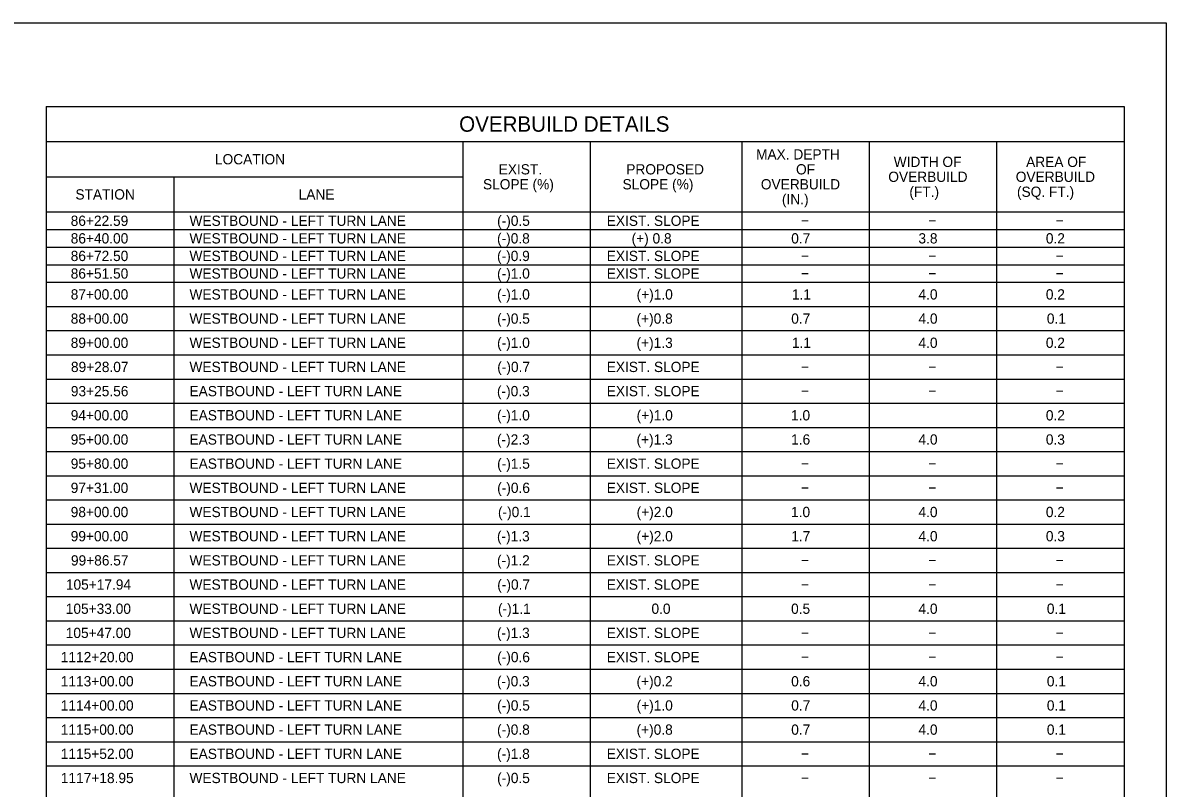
# Model space of a CAD drawing. Extents: x 0.03 to 1.66, y 0 to 0.87.
# Drawn here: x 0.679 to 1.329, y 0.436 to 0.871 of the extents above; entities that cross this region are included whole.
import ezdxf

# ---------------------------------------------------------------- set-up
doc = ezdxf.new("R2010")
doc.units = 0
for name, color, linetype in [('SheetBorder_dp', 7, 'Continuous'), ('SumBoxBorder_dp', 7, 'Continuous'), ('SumBoxLines_dp', 7, 'Continuous'), ('SumBoxLinesMin_dp', 7, 'Continuous'), ('TextLabel', 7, 'Continuous')]:
    doc.layers.add(name, color=color, linetype=linetype)

msp = doc.modelspace()

# ---------------------------------------------------------------- linework, layer by layer
at = {"layer": 'SheetBorder_dp'}
for p, q in [((0.04583, 0.87083), (1.32916, 0.87083)), ((1.32916, 0.87083), (1.32916, 0.00417))]:
    msp.add_line(p, q, dxfattribs=at)
at = {"layer": 'SumBoxBorder_dp'}
for p, q in [((0.69239, 0.82332), (1.30527, 0.82332)), ((1.30527, 0.82332), (1.30527, 0.10985)), ((1.30527, 0.82332), (1.30527, 0.10985))]:
    msp.add_line(p, q, dxfattribs=at)
at = {"layer": 'SumBoxLines_dp'}
for p, q in [((0.69239, 0.82332), (0.69239, 0.10985)), ((0.69239, 0.80332), (1.30527, 0.80332)), ((0.69239, 0.80332), (1.30527, 0.80332)), ((0.92917, 0.80332), (0.92917, 0.10985)), ((0.92917, 0.80332), (0.92917, 0.10985)), ((1.00164, 0.80332), (1.00164, 0.10985)), ((1.00164, 0.80332), (1.00164, 0.10985)), ((1.08785, 0.80332), (1.08785, 0.10985)), ((1.08785, 0.80332), (1.08785, 0.10985)), ((1.16032, 0.80332), (1.16032, 0.10985)), ((1.16032, 0.80332), (1.16032, 0.10985)), ((1.23279, 0.80332), (1.23279, 0.10985)), ((1.23279, 0.80332), (1.23279, 0.10985)), ((0.69239, 0.78333), (0.92917, 0.78333)), ((0.69239, 0.78333), (0.92917, 0.78333)), ((0.76486, 0.78333), (0.76486, 0.10985)), ((0.76486, 0.78333), (0.76486, 0.10985)), ((0.69239, 0.76334), (1.30527, 0.76334)), ((0.69239, 0.76334), (1.30527, 0.76334))]:
    msp.add_line(p, q, dxfattribs=at)
at = {"layer": 'SumBoxLinesMin_dp'}
for p, q in [((0.69239, 0.75334), (1.30527, 0.75334)), ((0.69239, 0.75334), (1.30527, 0.75334)), ((0.69239, 0.74335), (1.30527, 0.74335)), ((0.69239, 0.74335), (1.30527, 0.74335)), ((0.69239, 0.73335), (1.30527, 0.73335)), ((0.69239, 0.73335), (1.30527, 0.73335)), ((0.69239, 0.72336), (1.30527, 0.72336)), ((0.69239, 0.72336), (1.30527, 0.72336)), ((0.69239, 0.70961), (1.30527, 0.70961)), ((0.69239, 0.70961), (1.30527, 0.70961)), ((0.69239, 0.69587), (1.30527, 0.69587)), ((0.69239, 0.69587), (1.30527, 0.69587)), ((0.69239, 0.68212), (1.30527, 0.68212)), ((0.69239, 0.68212), (1.30527, 0.68212)), ((0.69239, 0.66838), (1.30527, 0.66838)), ((0.69239, 0.66838), (1.30527, 0.66838)), ((0.69239, 0.65463), (1.30527, 0.65463)), ((0.69239, 0.65463), (1.30527, 0.65463)), ((0.69239, 0.64089), (1.30527, 0.64089)), ((0.69239, 0.64089), (1.30527, 0.64089)), ((0.69239, 0.62714), (1.30527, 0.62714)), ((0.69239, 0.62714), (1.30527, 0.62714)), ((0.69239, 0.6134), (1.30527, 0.6134)), ((0.69239, 0.6134), (1.30527, 0.6134)), ((0.69239, 0.59966), (1.30527, 0.59966)), ((0.69239, 0.59966), (1.30527, 0.59966)), ((0.69239, 0.58591), (1.30527, 0.58591)), ((0.69239, 0.58591), (1.30527, 0.58591)), ((0.69239, 0.57217), (1.30527, 0.57217)), ((0.69239, 0.57217), (1.30527, 0.57217)), ((0.69239, 0.55842), (1.30527, 0.55842)), ((0.69239, 0.55842), (1.30527, 0.55842)), ((0.69239, 0.54468), (1.30527, 0.54468)), ((0.69239, 0.54468), (1.30527, 0.54468)), ((0.69239, 0.53093), (1.30527, 0.53093)), ((0.69239, 0.53093), (1.30527, 0.53093)), ((0.69239, 0.51719), (1.30527, 0.51719)), ((0.69239, 0.51719), (1.30527, 0.51719)), ((0.69239, 0.50344), (1.30527, 0.50344)), ((0.69239, 0.50344), (1.30527, 0.50344)), ((0.69239, 0.4897), (1.30527, 0.4897)), ((0.69239, 0.4897), (1.30527, 0.4897)), ((0.69239, 0.47596), (1.30527, 0.47596)), ((0.69239, 0.47596), (1.30527, 0.47596)), ((0.69239, 0.46221), (1.30527, 0.46221)), ((0.69239, 0.46221), (1.30527, 0.46221)), ((0.69239, 0.44847), (1.30527, 0.44847)), ((0.69239, 0.44847), (1.30527, 0.44847))]:
    msp.add_line(p, q, dxfattribs=at)

# ---------------------------------------------------------------- texts
at = {"layer": 'TextLabel'}
for s, height, p in [('OVERBUILD DETAILS', 0.0087465, (0.92717, 0.80895)), ('LOCATION', 0.005831, (0.78831, 0.79041)), ('MAX. DEPTH', 0.005831, (1.09598, 0.79316)), ('WIDTH OF', 0.005831, (1.17425, 0.78891)), ('AREA OF', 0.005831, (1.24955, 0.78891)), ('EXIST.', 0.005831, (0.94963, 0.78467)), ('PROPOSED', 0.005831, (1.02219, 0.78467)), ('OF', 0.005831, (1.11871, 0.78467)), ('SLOPE (%)', 0.005831, (0.94072, 0.77617)), ('SLOPE (%)', 0.005831, (1.02007, 0.77617)), ('OVERBUILD', 0.005831, (1.09871, 0.77617)), ('OVERBUILD', 0.005831, (1.17118, 0.78042)), ('OVERBUILD', 0.005831, (1.24365, 0.78042)), ('STATION', 0.005831, (0.70897, 0.77042)), ('LANE', 0.005831, (0.83591, 0.77042)), ('(IN.)', 0.005831, (1.1107, 0.76767)), ('(FT.)', 0.005831, (1.18317, 0.77192)), ('(SQ. FT.)', 0.005831, (1.24435, 0.77192)), ('86+22.59', 0.005831, (0.70628, 0.75543)), ('WESTBOUND - LEFT TURN LANE', 0.005831, (0.77383, 0.75543)), ('(-)0.5', 0.005831, (0.94875, 0.75543)), ('EXIST. SLOPE', 0.005831, (1.01107, 0.75543)), ('−', 0.00583, (1.12147, 0.75543)), ('−', 0.00583, (1.19394, 0.75543)), ('−', 0.00583, (1.26641, 0.75543)), ('86+40.00', 0.005831, (0.7063, 0.74543)), ('WESTBOUND - LEFT TURN LANE', 0.005831, (0.77383, 0.74543)), ('(-)0.8', 0.005831, (0.9487, 0.74543)), ('(+) 0.8', 0.005831, (1.02522, 0.74543)), ('0.7', 0.005831, (1.11599, 0.74543)), ('3.8', 0.005831, (1.18832, 0.74543)), ('0.2', 0.005831, (1.26077, 0.74543)), ('86+72.50', 0.005831, (0.7063, 0.73543)), ('WESTBOUND - LEFT TURN LANE', 0.005831, (0.77383, 0.73543)), ('(-)0.9', 0.005831, (0.94871, 0.73543)), ('EXIST. SLOPE', 0.005831, (1.01107, 0.73543)), ('−', 0.00583, (1.12147, 0.73543)), ('−', 0.00583, (1.19394, 0.73543)), ('−', 0.00583, (1.26641, 0.73543)), ('86+51.50', 0.005831, (0.7063, 0.72544)), ('WESTBOUND - LEFT TURN LANE', 0.005831, (0.77383, 0.72544)), ('(-)1.0', 0.005831, (0.94872, 0.72544)), ('EXIST. SLOPE', 0.005831, (1.01107, 0.72544)), ('−', 0.00583, (1.12147, 0.72544)), ('−', 0.00583, (1.19394, 0.72544)), ('−', 0.00583, (1.26641, 0.72544)), ('87+00.00', 0.005831, (0.7063, 0.71357)), ('WESTBOUND - LEFT TURN LANE', 0.005831, (0.77383, 0.71357)), ('(-)1.0', 0.005831, (0.94872, 0.71357)), ('(+)1.0', 0.005831, (1.02807, 0.71357)), ('1.1', 0.005831, (1.11639, 0.71357)), ('4.0', 0.005831, (1.18835, 0.71357)), ('0.2', 0.005831, (1.26077, 0.71357)), ('88+00.00', 0.005831, (0.7063, 0.69982)), ('WESTBOUND - LEFT TURN LANE', 0.005831, (0.77383, 0.69982)), ('(-)0.5', 0.005831, (0.94875, 0.69982)), ('(+)0.8', 0.005831, (1.02804, 0.69982)), ('0.7', 0.005831, (1.11599, 0.69982)), ('4.0', 0.005831, (1.18835, 0.69982)), ('0.1', 0.005831, (1.26133, 0.69982)), ('89+00.00', 0.005831, (0.7063, 0.68608)), ('WESTBOUND - LEFT TURN LANE', 0.005831, (0.77383, 0.68608)), ('(-)1.0', 0.005831, (0.94872, 0.68608)), ('(+)1.3', 0.005831, (1.02802, 0.68608)), ('1.1', 0.005831, (1.11639, 0.68608)), ('4.0', 0.005831, (1.18835, 0.68608)), ('0.2', 0.005831, (1.26077, 0.68608)), ('89+28.07', 0.005831, (0.70642, 0.67234)), ('WESTBOUND - LEFT TURN LANE', 0.005831, (0.77383, 0.67234)), ('(-)0.7', 0.005831, (0.94884, 0.67234)), ('EXIST. SLOPE', 0.005831, (1.01107, 0.67234)), ('−', 0.00583, (1.12147, 0.67234)), ('−', 0.00583, (1.19394, 0.67234)), ('−', 0.00583, (1.26641, 0.67234)), ('93+25.56', 0.005831, (0.70637, 0.65859)), ('EASTBOUND - LEFT TURN LANE', 0.005831, (0.77383, 0.65859)), ('(-)0.3', 0.005831, (0.94867, 0.65859)), ('EXIST. SLOPE', 0.005831, (1.01107, 0.65859)), ('−', 0.00583, (1.12147, 0.65859)), ('−', 0.00583, (1.19394, 0.65859)), ('−', 0.00583, (1.26641, 0.65859)), ('94+00.00', 0.005831, (0.7063, 0.64485)), ('EASTBOUND - LEFT TURN LANE', 0.005831, (0.77383, 0.64485)), ('(-)1.0', 0.005831, (0.94872, 0.64485)), ('(+)1.0', 0.005831, (1.02807, 0.64485)), ('1.0', 0.005831, (1.11588, 0.64485)), ('0.2', 0.005831, (1.26077, 0.64485)), ('(-)2.3', 0.005831, (0.94867, 0.6311)), ('(+)1.3', 0.005831, (1.02802, 0.6311)), ('95+00.00', 0.005831, (0.7063, 0.6311)), ('EASTBOUND - LEFT TURN LANE', 0.005831, (0.77383, 0.6311)), ('1.6', 0.005831, (1.11594, 0.6311)), ('4.0', 0.005831, (1.18835, 0.6311)), ('0.3', 0.005831, (1.26077, 0.6311)), ('95+80.00', 0.005831, (0.7063, 0.61736)), ('EASTBOUND - LEFT TURN LANE', 0.005831, (0.77383, 0.61736)), ('(-)1.5', 0.005831, (0.94875, 0.61736)), ('EXIST. SLOPE', 0.005831, (1.01107, 0.61736)), ('−', 0.00583, (1.12147, 0.61736)), ('−', 0.00583, (1.19394, 0.61736)), ('−', 0.00583, (1.26641, 0.61736)), ('97+31.00', 0.005831, (0.7063, 0.60361)), ('WESTBOUND - LEFT TURN LANE', 0.005831, (0.77383, 0.60361)), ('(-)0.6', 0.005831, (0.94879, 0.60361)), ('EXIST. SLOPE', 0.005831, (1.01107, 0.60361)), ('−', 0.00583, (1.12147, 0.60361)), ('−', 0.00583, (1.19394, 0.60361)), ('−', 0.00583, (1.26641, 0.60361)), ('98+00.00', 0.005831, (0.7063, 0.58987)), ('WESTBOUND - LEFT TURN LANE', 0.005831, (0.77383, 0.58987)), ('(-)0.1', 0.005831, (0.94924, 0.58987)), ('(+)2.0', 0.005831, (1.02807, 0.58987)), ('1.0', 0.005831, (1.11588, 0.58987)), ('4.0', 0.005831, (1.18835, 0.58987)), ('0.2', 0.005831, (1.26077, 0.58987)), ('99+00.00', 0.005831, (0.7063, 0.57612)), ('WESTBOUND - LEFT TURN LANE', 0.005831, (0.77383, 0.57612)), ('(-)1.3', 0.005831, (0.94867, 0.57612)), ('(+)2.0', 0.005831, (1.02807, 0.57612)), ('1.7', 0.005831, (1.11599, 0.57612)), ('4.0', 0.005831, (1.18835, 0.57612)), ('0.3', 0.005831, (1.26077, 0.57612)), ('99+86.57', 0.005831, (0.70642, 0.56238)), ('WESTBOUND - LEFT TURN LANE', 0.005831, (0.77383, 0.56238)), ('(-)1.2', 0.005831, (0.94868, 0.56238)), ('EXIST. SLOPE', 0.005831, (1.01107, 0.56238)), ('−', 0.00583, (1.12147, 0.56238)), ('−', 0.00583, (1.19394, 0.56238)), ('−', 0.00583, (1.26641, 0.56238)), ('105+17.94', 0.005831, (0.70354, 0.54863)), ('WESTBOUND - LEFT TURN LANE', 0.005831, (0.77383, 0.54863)), ('(-)0.7', 0.005831, (0.94884, 0.54863)), ('EXIST. SLOPE', 0.005831, (1.01107, 0.54863)), ('−', 0.00583, (1.12147, 0.54863)), ('−', 0.00583, (1.19394, 0.54863)), ('−', 0.00583, (1.26641, 0.54863)), ('105+33.00', 0.005831, (0.70348, 0.53489)), ('WESTBOUND - LEFT TURN LANE', 0.005831, (0.77383, 0.53489)), ('(-)1.1', 0.005831, (0.94924, 0.53489)), ('0.0', 0.005831, (1.03653, 0.53489)), ('0.5', 0.005831, (1.1159, 0.53489)), ('4.0', 0.005831, (1.18835, 0.53489)), ('0.1', 0.005831, (1.26133, 0.53489)), ('105+47.00', 0.005831, (0.70348, 0.52115)), ('WESTBOUND - LEFT TURN LANE', 0.005831, (0.77383, 0.52115)), ('(-)1.3', 0.005831, (0.94867, 0.52115)), ('EXIST. SLOPE', 0.005831, (1.01107, 0.52115)), ('−', 0.00583, (1.12147, 0.52115)), ('−', 0.00583, (1.19394, 0.52115)), ('−', 0.00583, (1.26641, 0.52115)), ('1112+20.00', 0.005831, (0.70065, 0.5074)), ('EASTBOUND - LEFT TURN LANE', 0.005831, (0.77383, 0.5074)), ('(-)0.6', 0.005831, (0.94879, 0.5074)), ('EXIST. SLOPE', 0.005831, (1.01107, 0.5074)), ('−', 0.00583, (1.12147, 0.5074)), ('−', 0.00583, (1.19394, 0.5074)), ('−', 0.00583, (1.26641, 0.5074)), ('1113+00.00', 0.005831, (0.70065, 0.49366)), ('EASTBOUND - LEFT TURN LANE', 0.005831, (0.77383, 0.49366)), ('(-)0.3', 0.005831, (0.94867, 0.49366)), ('(+)0.2', 0.005831, (1.02802, 0.49366)), ('0.6', 0.005831, (1.11594, 0.49366)), ('4.0', 0.005831, (1.18835, 0.49366)), ('0.1', 0.005831, (1.26133, 0.49366)), ('1114+00.00', 0.005831, (0.70065, 0.47991)), ('EASTBOUND - LEFT TURN LANE', 0.005831, (0.77383, 0.47991)), ('(-)0.5', 0.005831, (0.94875, 0.47991)), ('(+)1.0', 0.005831, (1.02807, 0.47991)), ('0.7', 0.005831, (1.11599, 0.47991)), ('4.0', 0.005831, (1.18835, 0.47991)), ('0.1', 0.005831, (1.26133, 0.47991)), ('1115+00.00', 0.005831, (0.70065, 0.46617)), ('EASTBOUND - LEFT TURN LANE', 0.005831, (0.77383, 0.46617)), ('(-)0.8', 0.005831, (0.9487, 0.46617)), ('(+)0.8', 0.005831, (1.02804, 0.46617)), ('0.7', 0.005831, (1.11599, 0.46617)), ('4.0', 0.005831, (1.18835, 0.46617)), ('0.1', 0.005831, (1.26133, 0.46617)), ('1115+52.00', 0.005831, (0.70065, 0.45242)), ('EASTBOUND - LEFT TURN LANE', 0.005831, (0.77383, 0.45242)), ('(-)1.8', 0.005831, (0.9487, 0.45242)), ('EXIST. SLOPE', 0.005831, (1.01107, 0.45242)), ('−', 0.00583, (1.12147, 0.45242)), ('−', 0.00583, (1.19394, 0.45242)), ('−', 0.00583, (1.26641, 0.45242)), ('1117+18.95', 0.005831, (0.70068, 0.43868)), ('WESTBOUND - LEFT TURN LANE', 0.005831, (0.77383, 0.43868)), ('(-)0.5', 0.005831, (0.94875, 0.43868)), ('EXIST. SLOPE', 0.005831, (1.01107, 0.43868)), ('−', 0.00583, (1.12147, 0.43868)), ('−', 0.00583, (1.19394, 0.43868)), ('−', 0.00583, (1.26641, 0.43868))]:
    msp.add_text(s, height=height, dxfattribs=at).set_placement(p)

doc.saveas('drawing.dxf')
